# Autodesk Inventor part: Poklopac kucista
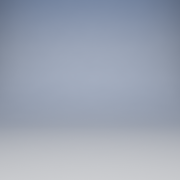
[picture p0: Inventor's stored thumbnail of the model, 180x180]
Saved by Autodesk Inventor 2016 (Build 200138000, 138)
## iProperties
Created: 2015-08
Part Number: Poklopac kucista
Material: Generic
Document SubType Name: Modeling
Designer: stank
Density: 1 g/cm^3
Appearance: Default
Author: stank
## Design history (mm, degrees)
